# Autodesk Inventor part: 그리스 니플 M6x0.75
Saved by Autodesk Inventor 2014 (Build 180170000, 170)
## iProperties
Created: 2026-03
Part Number: 그리스 니플 M6x0.75
Material: 강철, 연강
Document SubType Name: Modeling
Designer: dg
Density: 7.86 g/cm^3
Appearance: 강철
Mass: 2.06032 g
Surface Area: 3.27411 cm^2
Volume: 0.262127 cm^3
Author: jhkim
Description: 윤활 니플, 원추 유형 A
Creation Date: 2025-06-27
Sending System: Autodesk Inventor 2026
Preprocessor: ST-DEVELOPER v20.1
Author: dg
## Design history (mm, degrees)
node "그리스 니플 M6x0.751"
body "Solid1"
node "기준1"
